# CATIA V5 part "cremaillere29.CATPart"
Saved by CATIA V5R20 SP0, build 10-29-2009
Part number: cremaillere_29
Definition: NONE
Nomenclature: 1
Source: Unknown
Description: PART-1-DESC
Bounding box of the stored display mesh (mm): x -20 to 43, y -2 to 20, z -8 to 8
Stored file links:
  F:\Catia_finish\cremaillere29.CATPart
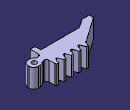
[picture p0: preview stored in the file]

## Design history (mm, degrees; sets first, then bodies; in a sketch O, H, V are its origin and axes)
Set1
  Sketch1 on xy-plane, origin (0, 0, 0), H (1, 0, 0), V (0, 1, 0)
    line L1 (1065, -108) -> (30, -108)
    line L2 (30, -108) -> (30, 187)
    line L3 (30, 187) -> (1065, 187)
    line L4 (1065, 187) -> (1065, -108)
    distance L2 V = 30
    horizontal: L1 H, L3 H
    vertical: L2 V, L4 V
Body1 "1" (main body)
  Solid1: solid without history
  Pocket1: profile Sketch1, direction (0, 0, -1), length 20, opposite side length 16
  Sketch2 on face of Solid1, origin (0, 0, 0), H (0, -1, 0), V (0, 0, 1)
    point P1 (0, 8)
    line L1 (0, 8) -> (-15.6, 8)
    line L2 (-15.6, 8) -> (-15.6, -8)
    line L3 (-15.6, -8) -> (0, -8)
    line L4 (0, -8) -> (0, 8)
    reference projected line E1 (-15.6, -8) -> (0, -8) from edge [face of Solid1 | face of Solid1]
    reference projected line E2 (-15.6, 8) -> (0, 8) from edge [face of Solid1 | face of Solid1]
    reference projected line E3 (-15.6, 8) -> (-15.6, -8) from edge [face of Solid1 | face of Solid1]
    coincidence: P1 V, L3 E1, L1 E2, L2 E3
    horizontal: L1 H, L3 H
    vertical: L2 V, L4 V
  Pad1: profile Sketch2, direction (-1, 0, 0), length 20
  Chamfer1: length 20, angle 35, on edge [face of Pad1 | end face of Pad1]
  Sketch3 on face of Pocket1 from Sketch1.L2, origin (30, 0, 0), H (0, 1, 0), V (0, 0, 1)
    line L1 (5, 8) -> (14, 8)
    line L2 (14, 8) -> (14, -8)
    line L3 (14, -8) -> (5, -8)
    line L4 (5, -8) -> (5, 8)
    reference projected line E1 (18.913, 8) -> (0, 8) from edge [face of Pad1 | face of Pocket1 from Sketch1.L2]
    reference projected line E2 (18.913, -8) -> (0, -8) from edge [face of Pocket1 from Sketch1.L2 | face of Pad1]
    reference projected line E3 (0, 8) -> (0, -8) from edge [face of Pad1 | face of Pocket1 from Sketch1.L2]
    length L3 = 9
    distance L4 E3 = 5
    horizontal: L1 H, L3 H
    vertical: L2 V, L4 V
    coincidence: L1 E1, L3 E2
  Pad2: profile Sketch3, direction (1, 0, 0), length 13
  Sketch4 on face of Pad2, origin (44, 9.5, 8), H (1, 0, 0), V (0, 1, 0)
    point P1 (-6, 0)
    reference projected point E1 (-6, 0) from Sketch7.P1
    coincidence: E1 P1
  Hole1: placed by Sketch4, at (38, 9.5, 8) direction (0, 0, -1), diameter 4, through (limit type 3)
  Sketch5 on face of Pad2, origin (0, 0, 8), H (1, 0, 0), V (0, 1, 0)
    line L1 (30, 7) -> (35, 7)
    line L2 (35, 7) -> (35, 5)
    line L3 (35, 5) -> (30, 5)
    line L4 (30, 5) -> (30, 7)
    line L5 (30, 14) -> (35, 14)
    line L6 (35, 14) -> (35, 12)
    line L7 (35, 12) -> (30, 12)
    line L8 (30, 12) -> (30, 14)
    reference projected line E1 (30, 14) -> (48, 14) from edge [face of Pad2 | face of Pad2 from Sketch3.L2]
    reference projected line E2 (30, 18.913) -> (30, 0) from edge [face of Pad2 | face of Pocket1 from Sketch1.L2]
    distance L7 L1 = 5
    distance L1 L3 = 2
    distance L7 L5 = 2
    length L3 = 5
    horizontal: L1 H, L3 H, L5 H, L7 H
    vertical: L2 V, L4 V, L6 V, L8 V
    coincidence: L5 E1, L6 L2, L4 L8, L8 E2
  Pocket2: profile Sketch5, direction (0, 0, -1), through (limit type 3)
  Fillet1: radius 2, on edge [face of Pocket2 from Sketch5.L1 | face of Pocket2 from Sketch5.L2]; edge [face of Pocket2 from Sketch5.L6 | face of Pocket2 from Sketch5.L7]
  Fillet2: radius 2, on edge [face of Pocket2 | face of Pocket2 from Sketch5.L1]; edge [face of Pocket2 from Sketch5.L7 | face of Pocket2]
  Fillet3: radius 4, on edge [face of Pad2 from Sketch3.L4 | face of Fillet1]; edge [face of Fillet1 | face of Pad2 from Sketch3.L2]; edge [face of Pad2 from Sketch3.L2 | end face of Pad2]; edge [face of Pad2 from Sketch3.L4 | end face of Pad2]
  Pad3: profile face of Pad1, direction along edge [face of Pad2 | end face of Pad1] reversed, length 2
  Sketch6 on face of Pad3, origin (0, 0, 8), H (1, 0, 0), V (0, 1, 0)
    line L1 (-14, 3) -> (26, 3)
    line L2 (26, 3) -> (26, -2)
    line L3 (26, -2) -> (-14, -2)
    line L4 (-14, -2) -> (-14, 3)
    reference projected line E1 (-20, -2) -> (30, -2) from edge [end face of Pad3 | face of Pad3]
    reference projected line E2 (30, 5) -> (30, -1) from edge [face of Pad3 | face of Pad3]
    reference projected line E3 (-20, 0) -> (-20, 15.6) from edge [face of Pad3 | face of Pad3]
    distance L1 L3 = 5
    distance L2 E2 = 4
    distance L4 E3 = 6
    horizontal: L1 H, L3 H
    vertical: L2 V, L4 V
    coincidence: L3 E1
  Pocket3: profile Sketch6, direction (0, 0, -1), through (limit type 3)
  Chamfer2: length 5, angle 55, on edge [face of Pocket3 from Sketch6.L4 | face of Pocket3 from Sketch6.L1]
  Sketch7 on face of Pad2, origin (0, 0, 8), H (1, 0, 0), V (0, 1, 0)
    point P1 (38, 9.5)
    reference projected line E1 (30, 5) -> (48, 5) from edge [face of Pad2 from Sketch3.L4 | face of Pad2]
    reference projected line E2 (43, 14) -> (43, 5) from edge [face of Pad2 from Sketch3.L1 | end face of Pad2]
    distance P1 E1 = 4.5
    distance E2 P1 = 5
